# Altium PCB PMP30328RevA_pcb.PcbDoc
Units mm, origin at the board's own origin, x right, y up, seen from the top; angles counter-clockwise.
Board outline 43.18 x 40.64 mm, 2 copper layers (Top Layer, Bottom Layer), stack 1.575 mm thick; 38 components, 16 nets, 78 pads, 12 vias.
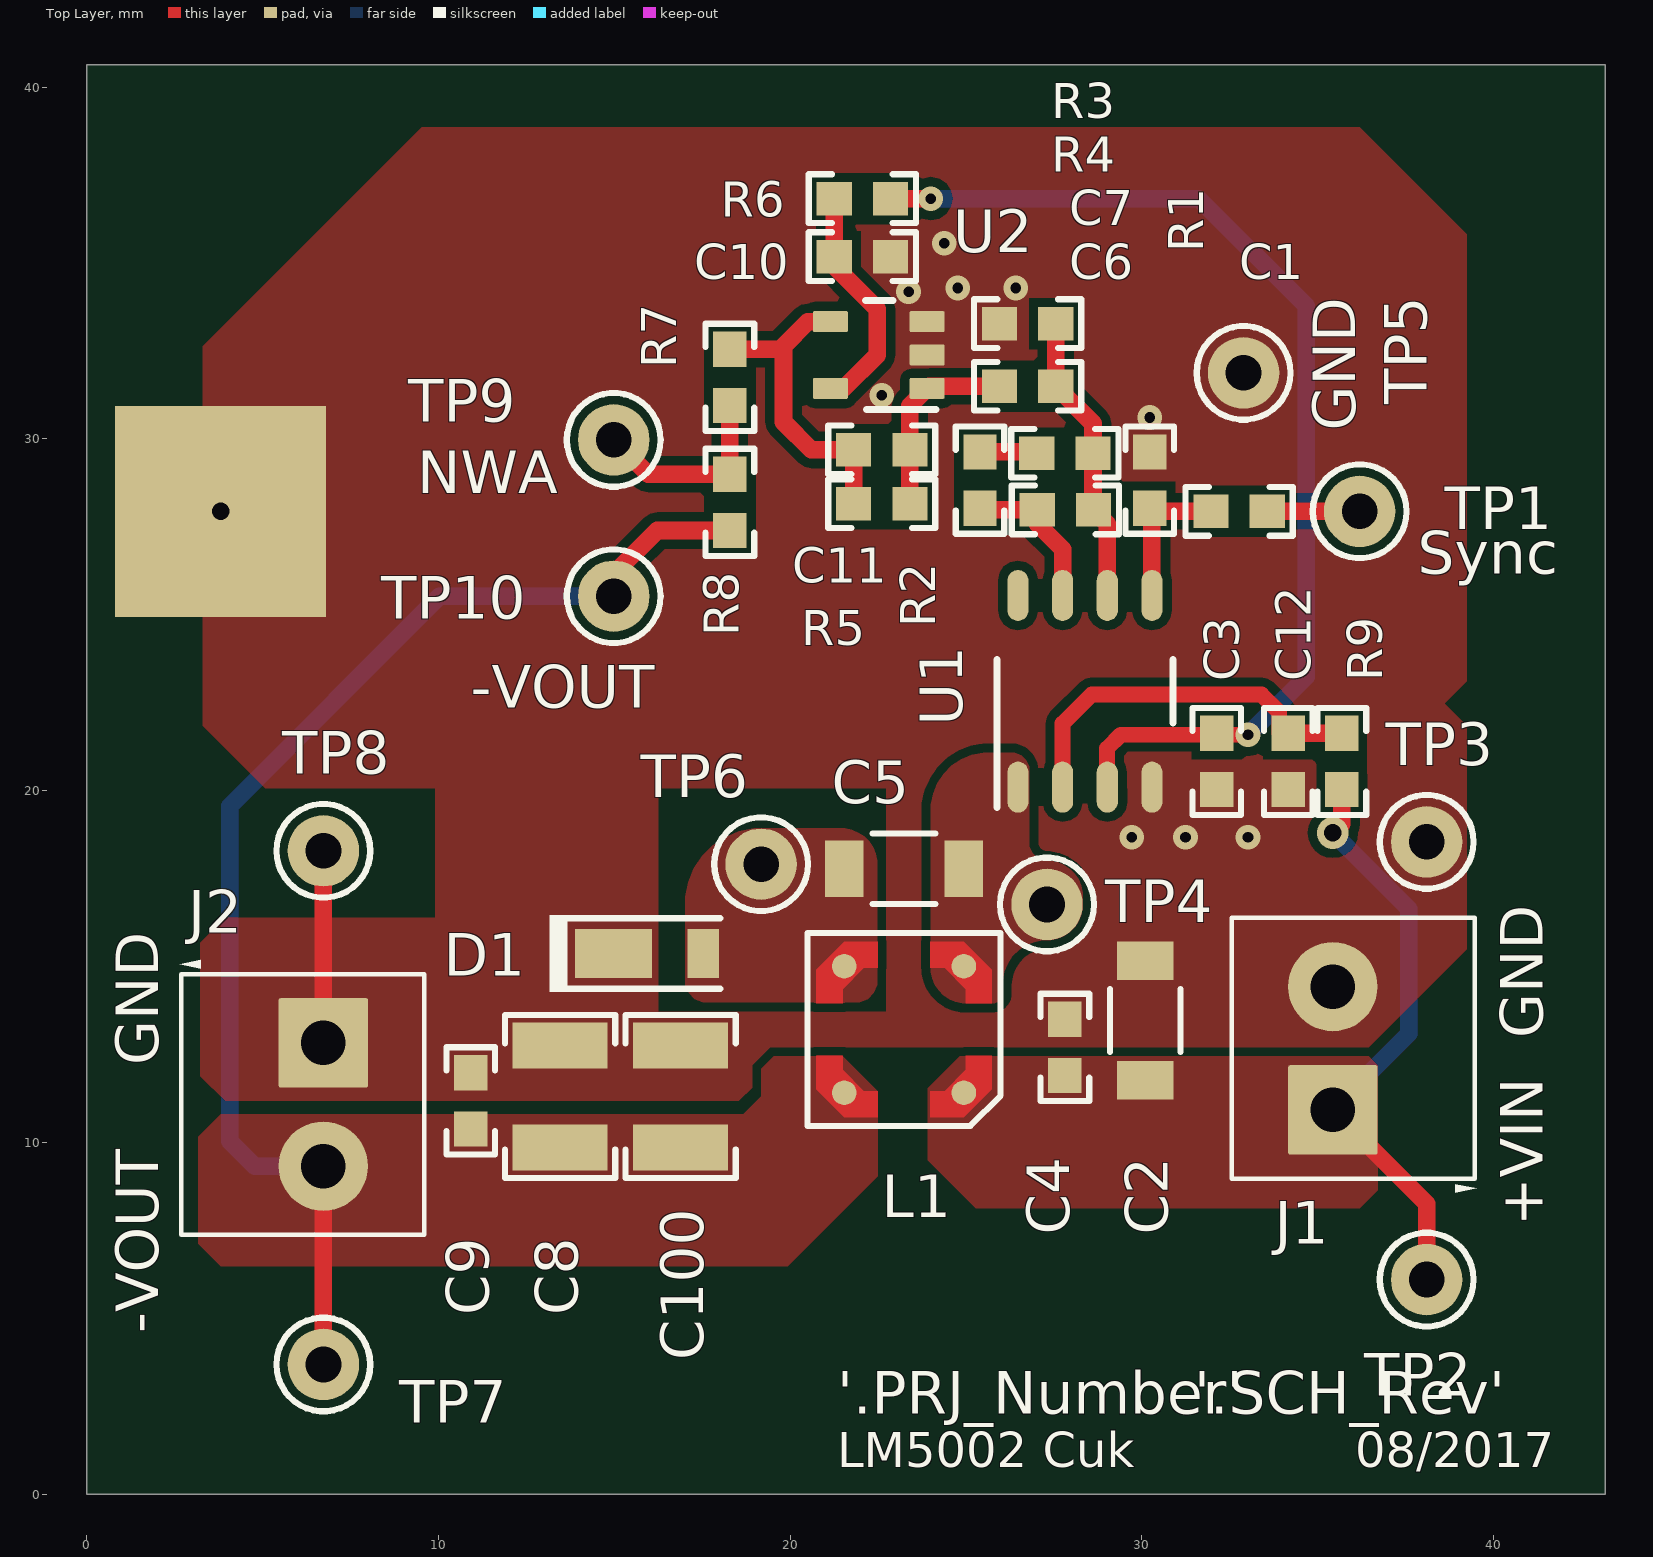
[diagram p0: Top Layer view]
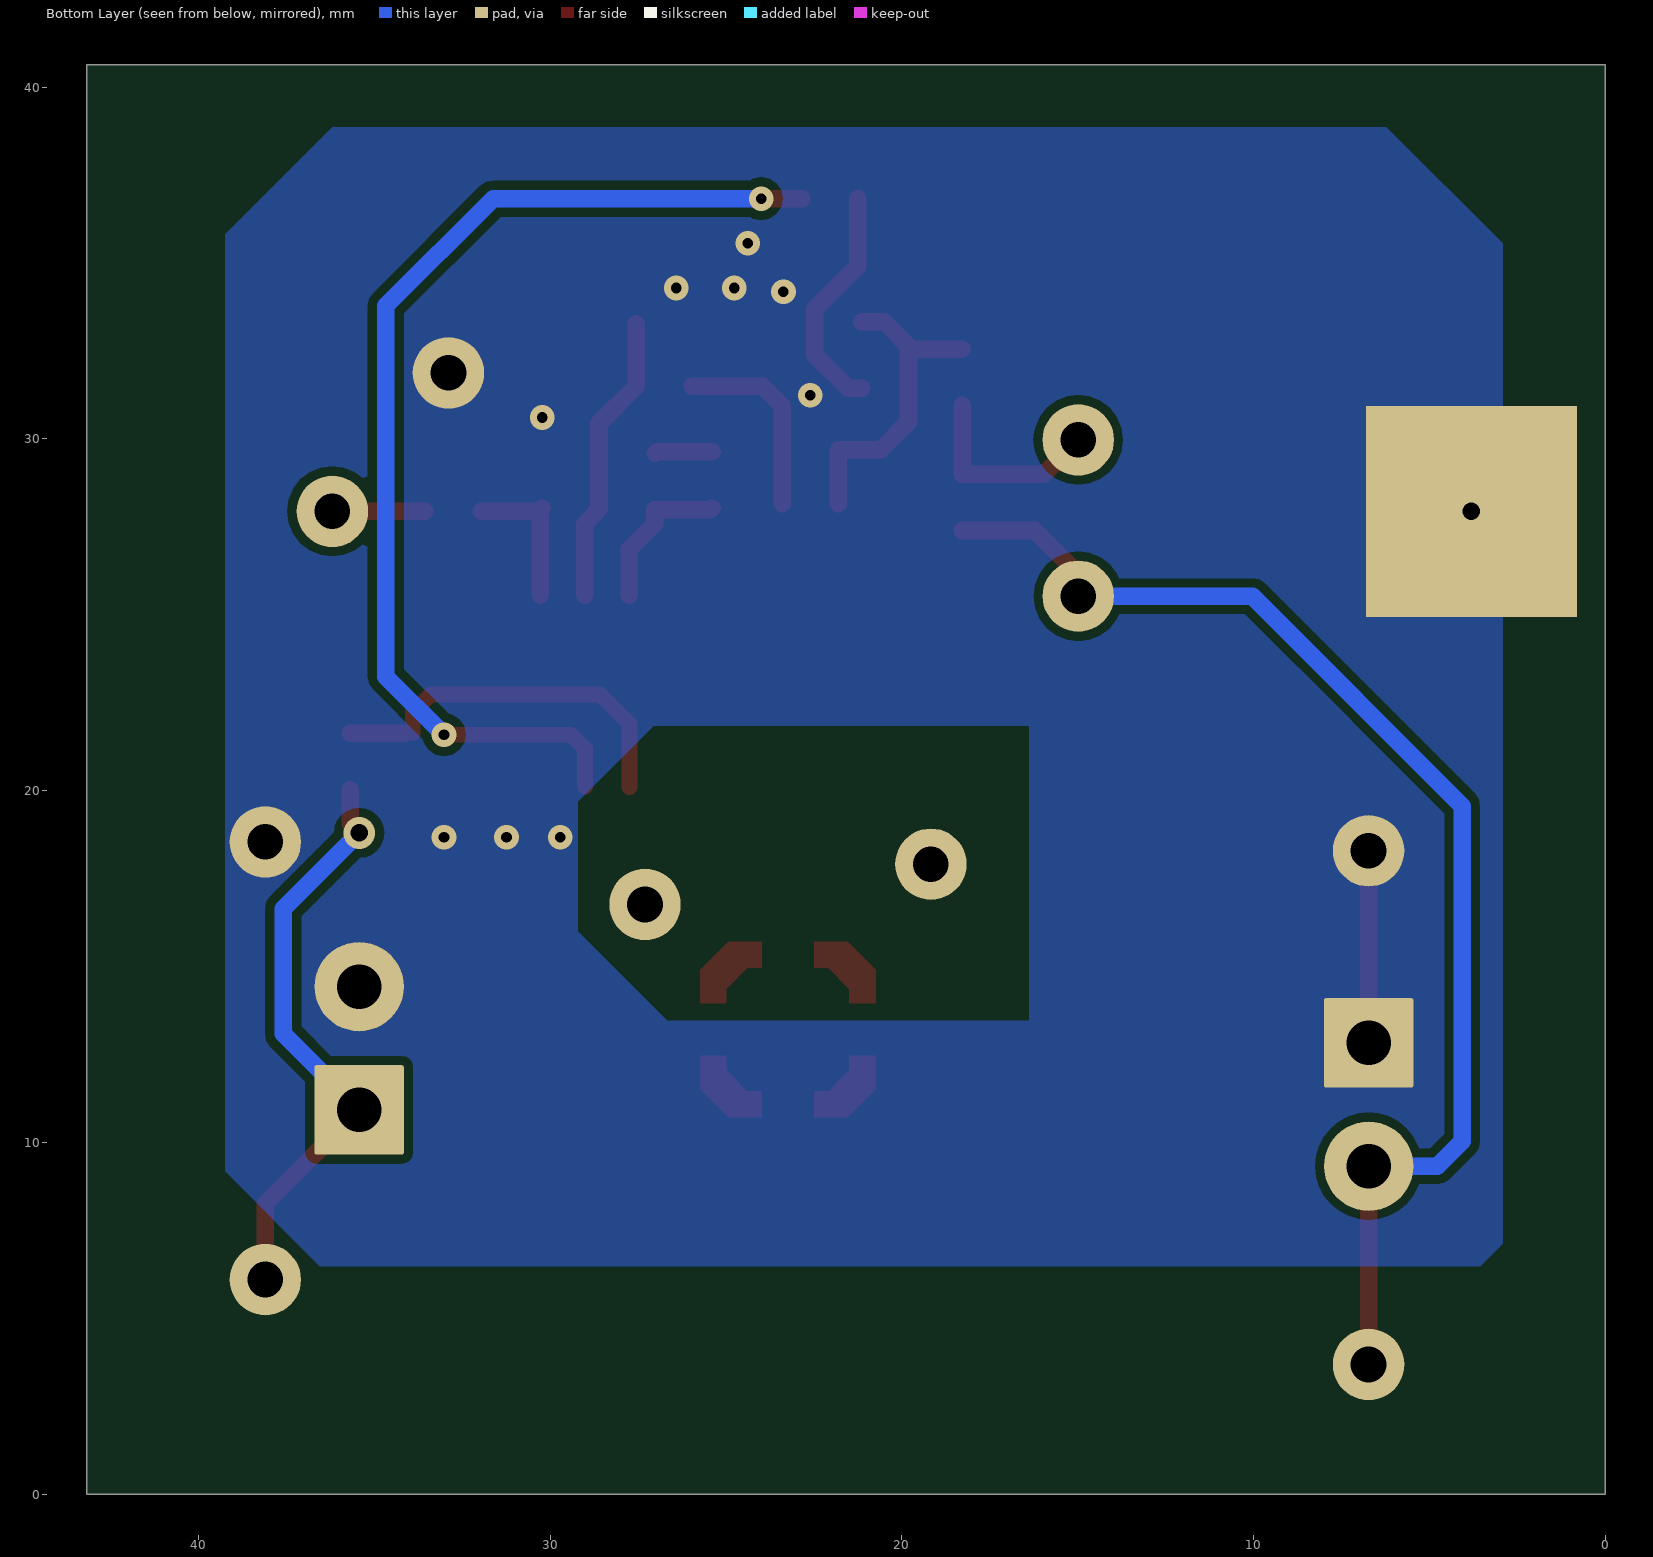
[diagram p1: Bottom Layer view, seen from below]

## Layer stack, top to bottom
Top Solder: solder mask 0.0102, Solder Resist, Dk 3.5
Top Layer: signal copper 0.0356
Dielectric1: core 1.5037, FR-4, Dk 4.8
Bottom Layer: signal copper 0.0356
Bottom Solder: solder mask 0.0102, Solder Resist, Dk 3.5

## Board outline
0,0 43.18,0 43.18,40.64 0,40.64

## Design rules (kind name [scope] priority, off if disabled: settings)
AcuteAngle [All] p1: minimum=4.50000000000000E+0001 checktracksonly=FALSE
AssemblyTestPointUsage [All] p1: valid=2
BoardOutlineClearance BoardOutlineClearance_MountingHoles [OnCopper and InComponentClass('Mounting Holes')] p1: gap=1.016 ignorepadtopadclearanceinfootprint=FALSE
BoardOutlineClearance BoardOutlineClearance_Poly [OnCopper and IsPoly] p2: gap=0.635 ignorepadtopadclearanceinfootprint=FALSE
BoardOutlineClearance [OnCopper and Not InComponentClass('Logo') and not InComponentClass('FiducialMark') and not InRegion(1000,500,4000,800) and not InPoly] p3: gap=1.905 ignorepadtopadclearanceinfootprint=FALSE
Clearance Clearance_Keepouts [((IsTrack Or IsArc) And Not InPoly) And IsFree and IsKeepOut vs ((IsTrack Or IsArc) And Not InPoly) And IsFree and IsKeepOut] p1: gap=0 ignorepadtopadclearanceinfootprint=FALSE
Clearance Clearance_Poly [InPolygon] p2: gap=0.254 ignorepadtopadclearanceinfootprint=FALSE except(0: Arc-Hole Track-Hole SMDPad-Hole THPad-Hole Via-Hole Fill-Hole Poly-Hole Region-Hole Text-Hole)
Clearance Clearance_FiducialMark [IsKeepOut and InComponentClass('FiducialMark') vs IsPad and InComponentClass('FiducialMark')] p3: gap=0 ignorepadtopadclearanceinfootprint=FALSE
Clearance [All] p4: gap=0.2 ignorepadtopadclearanceinfootprint=FALSE except(0: Text-Hole; 0.3: Arc-Hole Track-Hole SMDPad-Hole THPad-Hole Via-Hole Fill-Hole Poly-Hole Region-Hole)
ComponentClearance ComponentClearance_MountingHoles_FiducialMarks [InComponentClass('Mounting Holes') vs InComponentClass('FiducialMark')] p1: gap=1.27 collisioncheckmode=3 verticalgap=0.254 showdistances=FALSE
ComponentClearance ComponentClearance_Shunt [InComponentClass('Header') vs InComponentClass('Shunt')] p2: gap=0 collisioncheckmode=3 verticalgap=0 showdistances=FALSE
ComponentClearance ComponentClearance_Logo [InComponentClass('Logo')] p3: gap=1.27 collisioncheckmode=3 verticalgap=0.254 showdistances=FALSE
ComponentClearance ComponentClearance_ScrewToNut [(HasFootprint('NY PMS 440 0025 PH')) vs (HasFootprint('Keystone_1902C'))] p4: gap=0.127 collisioncheckmode=3 verticalgap=0.254 showdistances=FALSE
ComponentClearance ComponentClearance_MountingHoles [InComponentClass('Mounting Holes')] p5: gap=6.35 collisioncheckmode=3 verticalgap=2540 showdistances=FALSE
ComponentClearance ComponentClearance_SmallPassives [HasFootprint('0201*') or HasFootprint('0402*') or HasFootprint('0508') or HasFootprint('0603*') or HasFootprint('0612') or HasFootprint('0805*') or HasFootprint('0815*') or HasFootprint('0830*') or HasFootprint('1206*') or HasFootprint('1210*') or HasFootprint('1808*') or HasFootprint('1812*') or HasFootprint('1825*') or HasFootprint('2010*') or HasFootprint('2220*') or HasFootprint('2225*') or HasFootprint('2512*') or HasFootprint('2728*') or HasFootprint('3518*') vs HasFootprint('0201*') or HasFootprint('0402*') or HasFootprint('0508') or HasFootprint('0603*') or HasFootprint('0612') or HasFootprint('0805*') or HasFootprint('0815*') or HasFootprint('0830*') or HasFootprint('1206*') or HasFootprint('1210*') or HasFootprint('1808*') or HasFootprint('1812*') or HasFootprint('1825*') or HasFootprint('2010*') or HasFootprint('2220*') or HasFootprint('2225*') or HasFootprint('2512*') or HasFootprint('2728*') or HasFootprint('3518*')] p6: gap=0.38 collisioncheckmode=3 verticalgap=0.254 showdistances=FALSE
ComponentClearance ComponentClearance_THtoSMT [IsThruComponent vs IsSMTComponent] p7: gap=1.016 collisioncheckmode=3 verticalgap=0.762 showdistances=FALSE
ComponentClearance ComponentClearance_THtoTH [IsThruComponent vs IsThruComponent] p8: gap=0.762 collisioncheckmode=3 verticalgap=0.762 showdistances=FALSE
ComponentClearance [All] p9: gap=0.762 collisioncheckmode=3 verticalgap=0.254 showdistances=FALSE
DiffPairsRouting [All] p1: maxlimit=2.54 minlimit=0.254 mostfreqgap=0.254 toplayer_minwidth=0.381 toplayer_maxwidth=0.381 toplayer_prefwidth=0.381 bottomlayer_minwidth=0.381 bottomlayer_maxwidth=0.381 bottomlayer_prefwidth=0.381 maxuncoupledlength=25.4
FabricationTestPointUsage TestPointUsage [All] p1: valid=2 allowmultiple=FALSE
FabricationTestpoint Testpoint [All] p1: side=3 testpointundercomponent=TRUE minsize=1.016 maxsize=2.54 preferedsize=1.524 minholesize=0 maxholesize=1.016 preferedholesize=0.813 testpointgrid=0.025 allowsidetop=TRUE allowsidebottom=TRUE usegrid=TRUE gridtolerance=0
FanoutControl Fanout_LCC [IsLCC] p1: bgadir=Out bgaviamode=Centered fanoutstyle=Auto fanoutdirection=Alternating viagrid=0.025 // Fanout_LCC (Default Rule)
FanoutControl Fanout_BGA [IsBGA] p2: bgadir=Out bgaviamode=Centered fanoutstyle=Auto fanoutdirection=Alternating viagrid=0.025 // Fanout_BGA (Default Rule)
FanoutControl Fanout_Default [All] p4: bgadir=Out bgaviamode=Centered fanoutstyle=Auto fanoutdirection=Alternating viagrid=0.025 // Fanout_Default (Default Rule)
FanoutControl Fanout_Small [(CompPinCount < 5)] p5: bgadir=Out bgaviamode=Centered fanoutstyle=Auto fanoutdirection=OutThenIn viagrid=0.025 // Fanout_Small (Default Rule)
HoleSize [All] p1: absolutevalues=TRUE maxlimit=6.375 minlimit=0.3 maxpercent=80.000 minpercent=20.000
MinimumAnnularRing MinimumAnnularRing_ThermalPadVias [IsVia and InAnyComponent] p1: minimumring=0.15
MinimumAnnularRing [All] p2: minimumring=0.2
MinimumSolderMaskSliver MinimumSolderMaskSliver_Logo [InComponentClass('Logo') vs InComponentClass('Logo')] p1: minsoldermaskwidth=0.018
MinimumSolderMaskSliver [All] p2: minsoldermaskwidth=0.1
PlaneConnect [All] p1: planeconnectstyle=Relief reliefexpansion=0.254 reliefentries=4 reliefconductorwidth=0.254 reliefairgap=0.254
PolygonConnect [All] p1: connectstyle=Direct reliefconductorwidth=0.254 reliefentries=4 polygonreliefangle="90 Angle" airgapwidth=0.254
RoutingVias ThermalPadVias [IsVia and InAnyComponent] p1: holewidth=0.3 width=0.7 viastyle="Through Hole" minholewidth=0.3 minwidth=0.6 maxholewidth=0.6 maxwidth=1.6
RoutingVias [All] p2: holewidth=0.3 width=0.7 viastyle="Through Hole" minholewidth=0.3 minwidth=0.6 maxholewidth=1.016 maxwidth=2
SilkToBoardRegionClearance [Not ((IsComment or IsDesignator) And (Hide <> 'False')) and not InRegion(1000,500,4000,800)] p1:
SilkToSilkClearance SilkToSilkClearance_Pb-FreeLogo [(HasFootprint('Pb-Free_Overlay_Medium') OR HasFootprint('Pb-Free_Overlay_Small')) vs (HasFootprint('Pb-Free_Overlay_Medium') OR HasFootprint('Pb-Free_Overlay_Small'))] p1: silktosilkclearance=0
SilkToSilkClearance [All] p2: silktosilkclearance=0.102
SilkToSolderMaskClearance SilkToComponentPadClearance [(IsPad or IsFill or IsRegion) and InAnycomponent] p1: minsilkscreentomaskgap=0.127 clearancetoexposedcopper=TRUE
SilkToSolderMaskClearance "Silk to Solder Mask Opening" [All] p2: minsilkscreentomaskgap=0.102 clearancetoexposedcopper=FALSE
SolderMaskExpansion [All] p1: expansion=0.05
Width [All] p1: maxlimit=2.54 minlimit=0.152 preferedwidth=0.254 checkconnectedcopper=TRUE
15 further rules are at their usual default settings.

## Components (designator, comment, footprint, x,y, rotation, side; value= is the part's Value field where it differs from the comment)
C1 "GRM1885C1H101JA01D" 0603 32.766,27.94 r0 top value=100pF
C2 "GRM31CR72A225KA73L" 1206_190 30.099,13.462 r90 top value=2.2uF
C3 "GRM188R71E105KA12D" 0603 32.131,20.828 r270 top value=1uF
C4 "GRM188R72A104KA35D" 0603 27.813,12.7 r90 top value=0.1uF
C5 "GRM31CR72A105KA01L" 1206_180 23.241,17.78 r0 top value=1uF
C6 "GRM188R71H681KA01D" 0603 27.827,27.982 r180 top value=680pF
C7 "GRM188R71C334KA01D" 0603 27.813,29.591 r180 top value=0.33uF
C8 "GRM32ER71E226KE15L" 1210_270 13.462,11.303 r90 top value=22uF
C9 "GRM188R71E104KA01D" 0603 10.922,11.176 r90 top value=0.1uF
C10 "GRM188R71E105KA12D" 0603 22.055,35.179 r0 top value=1uF
C11 "GRM188R71H331KA01D" 0603 22.606,29.685 r0 top value=330pF
C12 "GRM188R72A104KA35D" 0603 34.163,20.828 r270 top value=0.1uF
C100 "GRM32ER71E226KE15L" 1210_270 16.891,11.303 r90 top value=22uF
D1 "DFLS1100-7" PowerDI123 16.256,15.367 r0 top value=100V
J1 "ED555/2DS" TERM_BLK_ED555-2DS 35.433,10.922 r90 top
J2 "ED555/2DS" TERM_BLK_ED555-2DS 6.731,12.827 r270 top
L1 "LPD5030V-154ME" LPD5030V 23.241,13.208 r180 top value=150uH
R1 "CRCW060342K2FKEA" 0603 30.226,28.829 r90 top value=42.2k
R2 "CRCW06034K64FKEA" 0603 25.4,28.829 r90 top value=4.64k
R3 "CRCW06033K32FKEA" 0603 26.754,33.274 r0 top value=3.32k
R4 "CRCW06034K64FKEA" 0603 26.754,31.496 r180 top value=4.64k
R5 "CRCW060310K0FKEA" 0603 22.606,28.161 r180 top value=10.0k
R6 "CRCW060310R0FKEA" 0603 22.055,36.83 r0 top value=10.0
R7 "CRCW060340K2FKEA" 0603 18.288,31.75 r270 top value=40.2k
R8 "CRCW060349R9FKEA" 0603 18.288,28.194 r270 top value=49.9
R9 "CRCW060310R0FKEA" 0603 35.687,20.828 r270 top value=10.0
TP1 "5002" Keystone5002 36.195,27.94 r270 top value=White
TP2 "5000" Keystone5000 38.1,6.096 r270 top value=Red
TP3 "5001" Keystone5001 38.1,18.542 r270 top value=Black
TP4 "5002" Keystone5002 27.305,16.764 r90 top value=White
TP5 "5001" Keystone5001 32.893,31.877 r90 top value=Black
TP6 "5002" Keystone5002 19.177,17.907 r90 top value=White
TP7 "5117" Keystone5117 6.731,3.683 r90 top value=Blue
TP8 "5001" Keystone5001 6.731,18.288 r90 top value=Black
TP9 "5004" Keystone5004 14.986,29.972 r90 top
TP10 "5000" Keystone5000 14.986,25.527 r90 top value=Red
U1 "LM5002MAX/NOPB" D0008A_N 28.384,22.823 r90 top
U2 "TLV271IDBVTG4" DBV0005A_N 22.521,32.385 r180 top

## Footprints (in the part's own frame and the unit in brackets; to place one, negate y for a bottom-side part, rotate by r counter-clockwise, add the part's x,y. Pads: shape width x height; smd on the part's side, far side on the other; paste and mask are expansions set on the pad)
0603 [mm] "0603 from SM-752 data"
  rect 1x0.95 smd: 1(-0.8,0) 2(0.8,0)
  silkscreen extent -1.52,-0.69 1.52,0.69, body extent -0.87,-0.47 0.87,0.47, height 1
1206_180 [mm] "1206_180"
  rect 1.1x1.6 smd: 1(-1.7,0) 2(1.7,0)
  silkscreen extent -0.9,-1 0.9,1, body extent -1.75,-0.95 1.75,0.95, height 1.8
1206_190 [mm] "1206_190"
  rect 1.1x1.6 smd: 1(-1.7,0) 2(1.7,0)
  silkscreen extent -0.9,-1 0.9,1, body extent -1.75,-0.95 1.75,0.95, height 1.9
1210_270 [mm] "1210"
  rect 1.3x2.7 smd: 1(-1.45,0) 2(1.45,0)
  silkscreen extent -2.32,-1.57 2.32,1.57, body extent -1.7,-1.35 1.7,1.35, height 2.7
D0008A_N [mm] "SOIC, 8-Leads, Body 4.9x3.9mm, Pitch 1.27mm, IPC Medium Density"
  oval 1.45x0.6 smd: 1(-2.725,1.905) 2(-2.725,0.635) 3(-2.725,-0.635) 4(-2.725,-1.905) 5(2.725,-1.905) 6(2.725,-0.635) 7(2.725,0.635) 8(2.725,1.905)
  silkscreen extent -3.3,-2.5 0.9,2.5, body extent -3,-2.45 3,2.45, height 1.63
DBV0005A_N [mm] "SOT23, 5-Leads, Body 2.9x1.6mm, Pitch 0.95mm, Lead Span 2.8mm, IPC Medium Density"
  rrect17% 1x0.6 smd: 1(-1.375,0.95) 2(-1.375,0) 3(-1.375,-0.95) 4(1.375,-0.95) 5(1.375,0.95)
  silkscreen extent -1.63,-1.55 0.38,1.55, body extent -1.42,-1.46 1.42,1.46, height 1.09
Keystone5000 [mil] "For Keystone 500x miniature loop terminals"
  round 80 hole 40: 1(0,0)
  silkscreen extent -52,-52 52,52, body extent -49,-49 49,49, height 182
Keystone5001 [mil] "For Keystone 500x miniature loop terminals"
  round 80 hole 40: 1(0,0)
  silkscreen extent -52,-52 52,52, body extent -49,-49 49,49, height 182
Keystone5002 [mil] "For Keystone 500x miniature loop terminals"
  round 80 hole 40: 1(0,0)
  silkscreen extent -52,-52 52,52, body extent -49,-49 49,49, height 182
Keystone5004 [mil] "For Keystone 500x miniature loop terminals"
  round 80 hole 40: 1(0,0)
  silkscreen extent -52,-52 52,52, body extent -49,-49 49,49, height 182
Keystone5117 [mil] "For Keystone 500x miniature loop terminals"
  round 80 hole 40: 1(0,0)
  silkscreen extent -52,-52 52,52, body extent -49,-49 49,49, height 182
LPD5030V [mm] "Coilcraft recommended land pattern Document 757-3 02/16/11"
  round 0.7 smd: 1(-1.7,1.8) 2(-1.7,-1.8) 3(1.7,-1.8) 4(1.7,1.8)
  Top Layer region: -1.7,-2.5 -2.5,-1.7 -2.5,-0.75 -1.75,-0.75 -1.75,-1.15 -1.15,-1.75 -0.75,-1.75 -0.75,-2.5
  Top Layer region: -2.5,0.75 -2.5,1.7 -1.7,2.5 -0.75,2.5 -0.75,1.75 -1.15,1.75 -1.75,1.15 -1.75,0.75
  Top Layer region: 0.75,1.75 0.75,2.5 1.7,2.5 2.5,1.7 2.5,0.75 1.75,0.75 1.75,1.15 1.15,1.75
  Top Layer region: 0.75,-2.5 0.75,-1.75 1.15,-1.75 1.75,-1.15 1.75,-0.75 2.5,-0.75 2.5,-1.7 1.7,-2.5
  silkscreen extent -2.74,-2.74 2.74,2.74, body extent -2.44,-2.44 2.44,2.44, height 3.02
PowerDI123 [mm] "Diodes Inc recommended land pattern, document number DS30628 Rev. 6-2"
  rect 2.2x1.4 smd: 1(-1.275,0)
  rect 0.9x1.4 smd: 2(1.275,0)
  silkscreen extent -3.1,-1.09 1.76,1.09, body extent -2.38,-0.97 1.52,0.96, height 1
TERM_BLK_ED555-2DS [mil]
  rrect4% 100x100 hole 50: 1(0,0)
  round 100 hole 50: 2(138,0)
  silkscreen extent -93,-161 215,113, body extent -69,-150 207,106, height 323

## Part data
C1: "CAP, CERM, 100 pF, 50 V,+/- 5%, C0G/NP0, 0603", Cap_Case=0603, Manufacturer=MuRata, Supplier Part Number 1=490-1427-1-ND, TempCo=C0G/NP0, Tolerance_%=5, Value1=Unknown, Value2=50V, ValueDisplayed=100pF
C2: "CAP, CERM, 2.2 µF, 100 V,+/- 10%, X7R, 1206", Cap_Case=1206, Manufacturer=MuRata, Supplier Part Number 1=490-7209-1-ND, TempCo=X7R, Tolerance_%=10, Value1=Unknown, Value2=100V, ValueDisplayed=2.2µF
C3 C10: "CAP, CERM, 1 µF, 25 V,+/- 10%, X7R, 0603", Cap_Case=0603, Manufacturer=MuRata, Supplier Part Number 1=490-5307-1-ND, TempCo=X7R, Tolerance_%=10, Value1=Unknown, Value2=25V, ValueDisplayed=1µF
C4 C12: "CAP, CERM, 0.1 µF, 100 V,+/- 10%, X7R, 0603", Cap_Case=0603, Manufacturer=MuRata, Supplier Part Number 1=490-3285-1-ND, TempCo=X7R, Tolerance_%=10, Value1=Unknown, Value2=100V, ValueDisplayed=0.1µF
C5: library part CMP-0008970-2, "CAP, CERM, 1 uF, 100 V, +/- 10%, X7R, 1206", Cap_Case=2220, Manufacturer=MuRata, Supplier Part Number 1=490-3909-1-ND, TempCo=X7R, Tolerance_%=10%, Value1=Unknown, Value2=100V, ValueDisplayed=1uF
C6: "CAP, CERM, 680 pF, 50 V,+/- 10%, X7R, 0603", Cap_Case=0603, Manufacturer=MuRata, Supplier Part Number 1=490-1491-1-ND, TempCo=X7R, Tolerance_%=10, Value1=Unknown, Value2=50V, ValueDisplayed=680pF
C7: "CAP, CERM, 0.33 µF, 16 V,+/- 10%, X7R, 0603", Cap_Case=0603, Manufacturer=MuRata, Supplier Part Number 1=490-3294-1-ND, TempCo=X7R, Tolerance_%=10, Value1=Unknown, Value2=16V, ValueDisplayed=0.33µF
C8 C100: "CAP, CERM, 22 µF, 25 V,+/- 10%, X7R, 1210", Cap_Case=1210, Manufacturer=MuRata, Supplier Part Number 1=490-5313-1-ND, TempCo=X7R, Tolerance_%=10, Value1="0.002334 ohm", Value2=25V, ValueDisplayed=22µF
C9: "CAP, CERM, 0.1 µF, 25 V,+/- 10%, X7R, 0603", Cap_Case=0603, Manufacturer=MuRata, Supplier Part Number 1=490-1524-1-ND, TempCo=X7R, Tolerance_%=10, Value2=25V, ValueDisplayed=0.1µF
C11: "CAP, CERM, 330 pF, 50 V,+/- 10%, X7R, 0603", Cap_Case=0603, Manufacturer=MuRata, Supplier Part Number 1=490-1486-1-ND, TempCo=X7R, Tolerance_%=10, Value1=Unknown, Value2=50V, ValueDisplayed=330pF
D1: "Diode, Schottky, 100 V, 1 A, PowerDI123", Manufacturer="Diodes Inc.", Supplier Part Number 1=DFLS1100DICT-ND, Value1=1A, Value2=0.77V
J1 J2: "Terminal Block, 6A, 3.5mm Pitch, 2-Pos, TH", Manufacturer="On-Shore Technology", Supplier Part Number 1=ED1514-ND
L1: "Coupled inductor, 150 µH, 0.29 A, 3.82 ohm, SMD", Manufacturer=Coilcraft, ValueDisplayed=150µH
R1: "RES, 42.2 k, 1%, 0.1 W, 0603", Manufacturer=Vishay-Dale, Power_W=0.1, Supplier Part Number 1=541-42.2KHCT-ND, TempCo="100 ppm/C", Tolerance_%=1, Value1=1%, Value2=0.1W, Value_Code=42k2, ValueDisplayed=42.2k
R2 R4: "RES, 4.64 k, 1%, 0.1 W, 0603", Manufacturer=Vishay-Dale, Power_W=0.1, Supplier Part Number 1=541-4.64KHCT-ND, TempCo="100 ppm/C", Tolerance_%=1, Value1=1%, Value2=0.1W, Value_Code=4k64, ValueDisplayed=4.64k
R3: "RES, 3.32 k, 1%, 0.1 W, 0603", Manufacturer=Vishay-Dale, Power_W=0.1, Supplier Part Number 1=541-3.32KHCT-ND, TempCo="100 ppm/C", Tolerance_%=1, Value1=1%, Value2=0.1W, Value_Code=3k32, ValueDisplayed=3.32k
R5: "RES, 10.0 k, 1%, 0.1 W, 0603", Manufacturer=Vishay-Dale, Power_W=0.1, Supplier Part Number 1=541-10.0KHCT-ND, TempCo="100 ppm/C", Tolerance_%=1, Value1=1%, Value2=0.1W, Value_Code=10k0, ValueDisplayed=10.0k
R6: "RES, 10.0, 1%, 0.1 W, 0603", Manufacturer=Vishay-Dale, Power_W=0.1, Supplier Part Number 1=541-10.0HCT-ND, TempCo="100 ppm/C", Tolerance_%=1, Value1=1%, Value2=0.1W, Value_Code=10R0, ValueDisplayed=10.0
R7: "RES, 40.2 k, 1%, 0.1 W, 0603", Manufacturer=Vishay-Dale, Power_W=0.1, Supplier Part Number 1=541-40.2KHCT-ND, TempCo="100 ppm/C", Tolerance_%=1, Value1=1%, Value2=0.1W, Value_Code=40k2, ValueDisplayed=40.2k
R8: "RES, 49.9, 1%, 0.1 W, 0603", Manufacturer=Vishay-Dale, Power_W=0.1, Supplier Part Number 1=541-49.9HCT-ND, TempCo="100 ppm/C", Tolerance_%=1, Value1=1%, Value2=0.1W, Value_Code=49R9, ValueDisplayed=49.9
R9: library part CMP-0022003-2, "RES, 10.0, 1%, 0.1 W, 0603", Manufacturer=Vishay-Dale, Power_W=100mW, Supplier Part Number 1=541-10.0HCT-ND, TempCo="100 ppm/C", Tolerance_%=1%, Value2=0.1W, Value_Code=10R0, ValueDisplayed=10.0
TP1 TP4 TP6: "Test Point, Miniature, White, TH", Manufacturer=Keystone, Supplier Part Number 1=5002K-ND
TP2 TP10: "Test Point, Miniature, Red, TH", Manufacturer=Keystone, Supplier Part Number 1=5000K-ND
TP3 TP5 TP8: "Test Point, Miniature, Black, TH", Manufacturer=Keystone, Supplier Part Number 1=5001K-ND
TP7: "Test Point, Miniature, Blue, TH", Color=Blue, Manufacturer=Keystone, Supplier Part Number 1=36-5117-ND
TP9: "Test Point, Miniature, Yellow, TH", Color=Yellow, Manufacturer=Keystone, Supplier Part Number 1=36-5004-ND
U1: library part CMP-0066117-1, "3.1-75V Wide Vin, 0.5A Current Mode Non-Synchronous Switch Mode Regulator, D0008A (SOIC-8)", Alternate Manufacturer="Texas Instruments"
U2: "550 uA/Ch, 3 MHz, Rail-to-Rail Output Operational Amplifier, 2.7 to 16 V, -40 to 125 degC, 5-pin SOT23 (DBV0005A), Green (RoHS & no Sb/Br)", Alternate Manufacturer="Texas Instruments", Alternate PartNumber=Equivalent, Rating=Catalog, Total Supply Voltage(Max)(+5V is 5, +/-5V is 10)=16, Total Supply Voltage(Min)(+5V is 5, +/-5V is 10)=2.7

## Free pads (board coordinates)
  rect 6x6 hole 0.5: 1(3.81,27.94)

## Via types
v1: diameter 0.7, hole 0.3, Top Layer to Bottom Layer, 8 vias
v2: diameter 0.7, hole 0.3, Top Layer to Bottom Layer, tented top, 3 vias
v3: diameter 0.9, hole 0.5, Top Layer to Bottom Layer, 1 vias

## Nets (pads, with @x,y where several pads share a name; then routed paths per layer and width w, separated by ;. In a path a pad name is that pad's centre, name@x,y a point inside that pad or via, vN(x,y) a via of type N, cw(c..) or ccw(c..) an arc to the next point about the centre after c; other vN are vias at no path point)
+6V9: C3.1 R6.2 U1.3 | length 31.2
  Top Layer w0.45: U1.3@29.009,20.108 29.009,21.198 29.401,21.59 v1(33.02,21.59)
  Top Layer w0.5: R6.2 v1(24.003,36.83)
  Bottom Layer w0.5: v1(24.003,36.83) 31.623,36.83 34.671,33.782 34.671,23.241 v1(33.02,21.59)
-12V0: C8.1 C9.1 C100.1 J2.2 L1.4 R8.2 TP7.1 TP10.1 | length 36
  Top Layer w0.5: TP7.1 J2.2 ; TP10.1 14.986,26.162 16.218,27.394 R8.2
  Bottom Layer w0.5: J2.2 4.775,9.322 4.064,10.033 4.064,19.558 10.033,25.527 TP10.1
GND: C2.2 C3.2 C4.2 C8.2 C9.2 C10.2 C12.2 C100.2 D1.1 J1.2 J2.1 pad.1 R1.2 R3.1 TP3.1 TP5.1 TP8.1 U1.4 U2.2 U2.3 | length 5.5
  Top Layer w0.5: J2.1 TP8.1
  other v1: 29.718,18.669 31.242,18.669 33.02,18.669 30.226,30.607 24.765,34.29 24.384,35.56
  other v2: 22.606,31.242 23.368,34.185 26.416,34.29
NetC1_1: C1.1 R1.1 U1.5 | length 4.2
  Top Layer w0.5: R1.1 R1.1@30.289,27.966 ; U1.5 R1.1@30.289,27.966 ; C1.1 30.315,27.94 R1.1@30.289,27.966
NetC1_2: C1.2 TP1.1 | length 2.6
  Top Layer w0.5: C1.2 TP1.1
NetC2_1: C2.1 C4.1 J1.1 L1.1 R9.2 TP2.1 | length 16.9
  Top Layer w0.5: J1.1 38.1,8.255 TP2.1 ; v3(35.433,18.796) 35.687,19.05 R9.2
  Bottom Layer w0.5: J1.1 37.592,13.081 37.592,16.637 v3(35.433,18.796)
NetC5_1: C5.1 D1.2 L1.3 TP6.1
NetC5_2: C5.2 L1.2 TP4.1 U1.1
NetC6_1: C6.1 C7.1 R3.2 R4.1 U1.6 | length 8.3
  Top Layer w0.5: R3.2 R4.1 28.613,30.437 C7.1 28.613,27.996 C6.1 29.019,27.59 U1.6
NetC6_2: C6.2 R2.1 U1.7 | length 4.4
  Top Layer w0.5: R2.1 25.447,27.982 C6.2 27.027,27.583 27.749,26.861 U1.7
NetC7_2: C7.2 R2.2 | length 1.6
  Top Layer w0.5: R2.2 26.975,29.629 C7.2
NetC10_1: C10.1 R6.1 U2.5 | length 6.7
  Top Layer w0.5: U2.5 21.529,31.435 22.479,32.385 22.479,33.692 21.255,34.916 C10.1 R6.1
NetC11_1: C11.1 R5.2 R7.1 U2.4 | length 9.2
  Top Layer w0.5: R7.1 19.723,32.55 19.812,32.639 ; U2.4 20.508,33.335 19.812,32.639 ; R5.2 C11.1 20.607,29.685 19.812,30.48 19.812,32.639
NetC11_2: C11.2 R4.2 R5.1 U2.1 | length 5.6
  Top Layer w0.5: R5.1 23.406,30.945 U2.1 23.957,31.496 R4.2
NetC12_1: C12.1 R9.1 U1.2 | length 10.6
  Top Layer w0.45: U1.2 27.749,21.907 28.575,22.733 33.401,22.733 33.909,22.225 C12.1@33.909,21.628
  Top Layer w0.5: C12.1 R9.1
NetR7_2: R7.2 R8.1 TP9.1 | length 5.7
  Top Layer w0.5: TP9.1 15.964,28.994 R8.1 R7.2
pads on no net: U1.8

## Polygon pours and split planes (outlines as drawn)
GND on Top Layer "TOP_LAYER_GND_P023" (solid, remove dead copper, pour order 23): 5.08,20.066 3.302,21.844 3.302,32.639 9.525,38.862 36.195,38.862 39.243,35.814 39.243,23.114 36.195,20.066
-12V0 on Top Layer "TOP_LAYER_-12V0_P013" (solid, remove dead copper, pour order 13): 22.491,11.458 22.491,9.029 19.939,6.477 3.81,6.477 3.175,7.112 3.175,10.16 3.81,10.795 16.637,10.795 18.669,10.795 19.177,11.303 19.177,12.192 19.443,12.458 21.491,12.458
GND on Top Layer "TOP_LAYER_GND_P011" (solid, remove dead copper, pour order 11): 24.384,12.7 19.431,12.7 18.923,12.192 18.923,11.557 18.542,11.176 3.937,11.176 3.231,11.882 3.231,15.677 3.937,16.383 16.256,16.383 16.256,13.716 24.384,13.716
NetC2_1 on Top Layer "TOP_LAYER_NETC2_1_P000" (solid, remove dead copper, pour order 0): 36.703,12.192 36.449,12.446 24.827,12.446 23.915,11.534 23.915,9.486 25.273,8.128 36.195,8.128 36.703,8.636
NetC5_2 on Top Layer "TOP_LAYER_NETC5_2_P015" (solid, remove dead copper, pour order 15): 26.035,14.478 cw(c27.305,14.478) 27.305,15.748 ccw(c27.305,16.764) 28.321,16.764 28.321,16.991 ccw(c27.302,16.991) 27.302,18.01 cw(c27.302,18.515) 26.797,18.515 26.797,20.574 ccw(c26.289,20.574) 26.289,21.082 25.654,21.082 ccw(c25.654,19.431) 24.003,19.431 24.003,14.946 ccw(c24.991,14.946) 24.991,13.958 25.769,13.958 ccw(c25.769,14.224) 26.035,14.224
NetC5_1 on Top Layer "TOP_LAYER_NETC5_1_P017" (solid, remove dead copper, pour order 17): 21.463,18.923 cw(c21.463,17.907) 22.479,17.907 22.479,14.605 cw(c21.844,14.605) 21.844,13.97 17.653,13.97 cw(c17.653,14.605) 17.018,14.605 17.018,16.764 cw(c19.177,16.764) 19.177,18.923
GND on Top Layer "TOP_LAYER_GND_P019" (solid, remove dead copper, pour order 19): 36.449,12.7 39.243,15.494 39.243,21.844 36.957,24.13 23.622,24.13 22.733,23.241 22.733,12.7
GND on Top Layer "TOP_LAYER_GND_P029" (solid, remove dead copper, pour order 29): 9.906,22.098 9.906,15.677 16.256,15.677 16.256,22.098
GND on Bottom Layer "BOTTOM_LAYER_GND_P027" (solid, remove dead copper, pour order 27): 2.921,34.798 14.605,34.798 16.383,33.02 16.383,8.128 14.732,6.477 3.556,6.477 2.921,7.112
GND on Bottom Layer "BOTTOM_LAYER_GND_P025" (solid, remove dead copper, pour order 25): 2.921,13.462 26.67,13.462 29.21,16.002 29.21,19.685 27.051,21.844 4.318,21.844 2.921,23.241 2.921,35.56 6.223,38.862 36.195,38.862 39.243,35.814 39.243,9.172 36.548,6.477 3.556,6.477 2.921,7.112

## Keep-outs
Keep-Out Layer:
  text ".Layer_Name" at 14.656,-21.806 h1.52

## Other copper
Top Layer:
  text ".Layer_Name" at 14.656,-21.806 h1.52
Bottom Layer:
  text ".Layer_Name" at 14.656,-21.806 h1.52

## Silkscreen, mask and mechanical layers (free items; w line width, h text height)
Top Overlay:
  text "GND" at 36.068,30.226 h1.2 r90
  text "NWA" at 9.398,28.448 h1.2
  text "Sync" at 37.846,26.162 h1.2
  text "-VOUT" at 10.922,22.352 h1.2
  text "GND" at 41.402,12.954 h1.2 r90
  text "GND" at 2.032,12.192 h1.2 r90
  text "+VIN" at 41.402,7.62 h1.2 r90
  text "-VOUT" at 2.032,4.572 h1.2 r90
  text "'.PRJ_Number'" at 21.336,2.286 h1.2
  text "'.SCH_Rev'" at 31.496,2.286 h1.2
  text "LM5002 Cuk" at 21.336,0.762 h1
  text "08/2017" at 36.068,0.762 h1
  text ".Layer_Name" at 14.656,-21.806 h1.52
Bottom Overlay:
  text ".Layer_Name" at 14.656,-21.806 h1.52
Top Paste:
  text ".Layer_Name" at 14.656,-21.806 h1.52
Bottom Paste:
  text ".Layer_Name" at 14.656,-21.806 h1.52
Top Solder:
  text ".Layer_Name" at 14.656,-21.806 h1.52
  text ".Layer_Name" at 14.656,-21.806 h1.52
Bottom Solder:
  text "'.SCH_Rev'" at 8.382,37.084 h1.2
  text "'.PRJ_Number'" at 19.05,37.084 h1.2
  text ".Layer_Name" at 14.656,-21.806 h1.52
Drill Guide:
  text ".Layer_Name" at 14.656,-21.806 h1.52
M1 Board Outline:
  the board outline again, w0.254
  text ".Layer_Name" at 14.656,-21.806 h1.52
M2 Board Dimensions:
  rectangle: 0,-6.985 3.175,-3.81
  rectangle: 3.175,-10.16 12.7,-6.985
  lines w0.178: 0,-6.985 25.4,-6.985 ; 3.175,-10.16 3.175,-3.81 ; 6.35,-10.16 6.35,-3.81 ; 12.7,-10.16 12.7,-3.81 ; 19.05,-10.16 19.05,-3.81 ; 0,-10.16 25.4,-10.16 25.4,-3.81 0,-3.81 0,-10.16
  text "'.Print_Date'" at 1.016,41.91 h1.52
  text "''.Print_Time''" at 16.637,41.91 h1.52
  text ".Layer_Name" at 14.656,-21.806 h1.52
M3 3D STEP Top:
  text ".Layer_Name" at 14.656,-21.806 h1.52
M4 3D STEP Bottom:
  text ".Layer_Name" at 14.656,-21.806 h1.52
M5 Assembly Top:
  lines w0.254: -7.417,-23.626 160.223,-23.626 ; -7.417,-18.462 160.274,-18.462 ; -7.417,-13.297 -7.417,-28.791 94.31,-28.791 160.274,-28.791 160.274,-13.297 -7.404,-13.297 -7.404,-28.791 32.614,-28.791 ; 55.194,-28.791 55.194,-13.297 ; 87.376,-18.462 87.376,-13.297 ; 108.712,-18.462 108.712,-13.297 ; 124.511,-28.956 124.511,-23.804
  text "COMPONENTS MARKED 'DNP' SHOULD NOT BE POPULATED." at 29.299,-8.09 h1.52
  text "ASSEMBLY VARIANT:" at 29.286,-11.024 h1.52
  text ".VariantName" at 55.601,-11.024 h1.52
  text "PCB VIEWED FROM TOP SIDE" at -5.804,-16.654 h1.52
  text "BOARD #:" at 57.099,-16.654 h1.52
  text ".PRJ_Number" at 70.955,-16.654 h1.52
  text "REV:" at 92.405,-16.654 h1.52
  text ".PCB_Rev" at 99.809,-16.654 h1.52
  text "SVN REV:" at 113.69,-16.654 h1.52
  text ".VersionControl_RevNumber" at 126.543,-16.654 h1.52
  text "TID #:" at 57.099,-21.819 h1.52
  text ".TID" at 70.955,-21.819 h1.52
  text "PLOT NAME =" at -5.804,-27.034 h1.52
  text ".plot_File_Name" at 14.656,-27.034 h1.52
  text "GENERATED    :" at 57.15,-27.034 h1.52
  text ".Print_Date" at 79.235,-27.034 h1.52
  text ".Print_Time" at 97.752,-27.034 h1.52
  text "TEXAS INSTRUMENTS" at 129.87,-27.034 h1.52
M6 Assembly Bottom:
  lines w0.254: -7.429,-18.474 160.261,-18.474 ; -7.379,-23.639 160.261,-23.639 ; 28.334,-28.969 28.334,-23.817 ; 44.133,-18.474 44.133,-13.31 ; 65.468,-18.474 65.468,-13.31 ; 97.65,-28.804 97.65,-13.31 ; 120.231,-28.804 160.249,-28.804 160.249,-13.31 -7.429,-13.31 -7.429,-28.804 58.534,-28.804 160.261,-28.804 160.261,-13.31
  text "COMPONENTS MARKED 'DNP' SHOULD NOT BE POPULATED." at 154.991,-8.077 h1.52
  text ".VariantName" at 128.473,-11.024 h1.52
  text "ASSEMBLY VARIANT:" at 154.864,-11.024 h1.52
  text ".VersionControl_RevNumber" at 26.302,-16.667 h1.52
  text "SVN REV:" at 39.154,-16.667 h1.52
  text ".PCB_Rev" at 53.035,-16.667 h1.52
  text "REV:" at 60.439,-16.667 h1.52
  text ".PRJ_Number" at 81.89,-16.667 h1.52
  text "BOARD #:" at 95.745,-16.667 h1.52
  text "PCB VIEWED FROM BOTTOM SIDE" at 158.648,-16.667 h1.52
  text ".TID" at 81.89,-21.831 h1.52
  text "TID #:" at 95.745,-21.831 h1.52
  text "TEXAS INSTRUMENTS" at 22.974,-27.047 h1.52
  text ".Print_Time" at 55.093,-27.047 h1.52
  text ".Print_Date" at 73.609,-27.047 h1.52
  text "GENERATED    :" at 95.694,-27.047 h1.52
  text ".plot_File_Name" at 138.189,-27.047 h1.52
  text "PLOT NAME =" at 158.648,-27.047 h1.52
M9 Title Sheet:
  drawing of 57 lines, arcs and shapes, not listed
  text "1" at 18.792,204.127 h1.78
  text "2" at 82.182,204.127 h1.78
  text "3" at 145.411,204.127 h1.78
  text "4" at 209.08,204.127 h1.78
  text "5" at 272.555,204.127 h1.78
  text "6" at 336.182,204.127 h1.78
  text "A" at -10.579,175.095 h1.78
  text "A" at 365.341,175.095 h1.78
  text "B" at -10.579,114.643 h1.78
  text "B" at 365.341,114.643 h1.78
  text "C" at -10.579,54.318 h1.78
  text "C" at 365.341,54.318 h1.78
  text "PROJECT TITLE:" at 288.125,7.048 h1.14
  text ".PRJ_Title" at 289.395,3.662 h1.78
  text "DESIGNED FOR:" at 288.125,-0.597 h1.14
  text ".PRJ_Customer" at 289.395,-4.153 h1.78
  text "D" at -10.579,-5.88 h1.78
  text "D" at 365.341,-5.88 h1.78
  text "FILE NAME:" at 288.125,-8.217 h1.14
  text ".PCB_File_Name_No_Path" at 289.395,-11.265 h1.78
  text "Texas Instruments (TI) and/or its licensors do not warrant the accuracy or completeness of this specification" at 161.9,-15.376 h1.14
  text "ENGINEER:" at 288.125,-15.583 h1.14
  text "LAYOUT BY:" at 326.352,-15.583 h1.14
  text "or any information contained therein. TI and/or its licensors do not warrant that this design will meet" at 160.757,-18.237 h1.14
  text ".PRJ_Engineer" at 289.395,-19.52 h1.78
  text ".PCB_Layout" at 327.635,-19.52 h1.78
  text "the specifications, will be suitable for your application or fit for any particular purpose, or will operate in" at 160.757,-21.099 h1.14
  text ".Layer_Name" at 14.656,-21.806 h1.52
  text "ALTIUM DESIGNER VERSION:" at 326.352,-23.457 h1.14
  text "an implementation. TI and/or its licensors do not warrant that the design is production worthy. You should" at 160.757,-23.961 h1.14
  text "completely validate and test your design implementation to confirm the system functionality for your application." at 161.9,-26.822 h1.14
  text ".print_Scale" at 289.395,-26.843 h1.78
  text ".Application_BuildNumber" at 327.635,-26.843 h1.78
  text "1" at 18.792,-32.093 h1.78
  text "2" at 82.182,-32.093 h1.78
  text "3" at 145.411,-32.093 h1.78
  text "4" at 209.08,-32.093 h1.78
  text "5" at 272.555,-32.093 h1.78
  text "6" at 336.182,-32.093 h1.78
M10 Fab Notes:
  drawing of 189 lines, arcs and shapes, not listed
  text "DESIGN INFORMATION" at 314.503,161.447 h1.52
  text "MIN. TRACK WIDTH:" at 298.131,158.091 h1.52
  text "8" at 325.976,158.091 h1.52
  text "MIL" at 329.907,158.091 h1.52
  text "MIN. CLEARANCE:" at 298.131,154.938 h1.52
  text "0.2" at 324.452,154.938 h1.52
  text "mm" at 329.907,154.938 h1.52
  text "MIN. VIA PAD SIZE:" at 298.131,151.785 h1.52
  text "24" at 325.214,151.785 h1.52
  text "MIL" at 329.907,151.785 h1.52
  text "0.05mm (2MIL)" at 315.784,148.486 h1.52
  text "MINIMUM ANNULAR RING" at 289.769,148.277 h1.52
  text "EXTERNAL" at 333.768,148.277 h1.52
  text "PER" at 294.849,145.48 h1.52
  text "IPC-D-275 CLASS 2 LEVEL C" at 300.437,145.48 h1.52
  text "MIL, HOLES" at 338.238,142.928 h1.52
  text "+/-" at 328.27,142.709 h1.52
  text "+/-" at 349.961,142.709 h1.52
  text "REGISTRATION TOLERANCES:" at 289.769,142.682 h1.52
  text "METAL" at 320.243,142.682 h1.52
  text "5" at 334.879,142.683 h1.52
  text "3" at 356.037,142.683 h1.52
  text "MIL" at 358.99,142.682 h1.52
  text "HOLE SIZE TOLERANCE (UNLESS OTHERWISE SPECIFIED):" at 289.769,140.185 h1.52
  text "+/-" at 349.961,140.112 h1.52
  text "3" at 356.037,140.085 h1.52
  text "MIL" at 358.99,140.085 h1.52
  text "MATERIAL:" at 287.87,136.589 h1.52
  text "FR-4 High Tg" at 312.926,133.324 h1.52
  text "X" at 309.257,133.122 h1.52
  text "FR-408" at 298.563,133.007 h1.52
  text "OTHER" at 336.358,133.007 h1.52
  text "62 MIL (1.6mm) +/-10%" at 306.694,129.374 h1.52
  text "X" at 303.643,129.312 h1.52
  text "THICKNESS:" at 289.769,129.165 h1.52
  text "OTHER" at 339.33,129.165 h1.52
  text "TOLERANCE:" at 289.769,125.652 h1.52
  text "X" at 311.314,125.652 h1.52
  text "ANSI IPC-6012 TYPE 3 CLASS 2" at 315.836,125.652 h1.52
  text "OTHER +/-" at 315.835,121.989 h1.52
  text "BOW & TWIST:" at 289.769,118.302 h1.52
  text "X" at 311.314,118.302 h1.52
  text "ANSI IPC-6012 TYPE 3 CLASS 2" at 315.836,118.302 h1.52
  text "OTHER +/-" at 315.835,114.576 h1.52
  text "DRILLING:" at 287.87,111.258 h1.52
  text "NC_DRILL FILES" at 332.599,108.586 h1.52
  text "REFERENCE:" at 289.769,108.486 h1.52
  text "X" at 306.463,108.484 h1.52
  text "AS SHOWN" at 310.984,108.486 h1.52
  text "X" at 329.348,108.486 h1.52
  text "OTHER" at 340.168,104.873 h1.52
  text "PTH COPPER THICKNESS:" at 289.761,104.783 h1.52
  text "X" at 318.697,104.783 h1.52
  text "20-30 um" at 321.948,104.783 h1.52
  text "BOARD FINISH:" at 287.87,101.034 h1.52
  text "SILKSCREEN:" at 291.812,98.237 h1.52
  text "X" at 316.14,98.237 h1.52
  text "TOP" at 319.112,98.237 h1.52
  text "X" at 329.094,98.237 h1.52
  text "BOTTOM" at 332.091,98.237 h1.52
  text "SILKSCREEN COLOR:" at 291.812,94.295 h1.52
  text "X" at 316.115,94.295 h1.52
  text "WHITE" at 319.112,94.295 h1.52
  text "OTHER" at 332.091,94.295 h1.52
  text "X" at 319.442,90.652 h1.52
  text "GREEN" at 322.439,90.652 h1.52
  text "OTHER" at 338.136,90.652 h1.52
  text "SOLDER RESIST COLOR:" at 291.812,90.477 h1.52
  text "X" at 319.442,86.734 h1.52
  text "MATTE" at 322.439,86.734 h1.52
  text "SEMI-GLOSS" at 338.125,86.717 h1.52
  text "IMMERSION GOLD (ENIG)" at 314.819,82.345 h1.52
  text "ENEPIG" at 348.793,82.162 h1.52
  text "SURFACE FINISH:" at 287.87,82.136 h1.52
  text "X" at 310.298,82.136 h1.52
  text "IMM. TIN/SILVER OR EQUIV" at 296.24,78.649 h1.52
  text "OTHER" at 332.599,78.549 h1.52
  text "ARRAY/PANEL:" at 287.87,74.602 h1.52
  text "CUT AND TRIM PER M1 BOARD OUTLINE" at 314.819,74.393 h1.52
  text "N.C. ROUTE" at 314.819,70.94 h1.52
  text "X" at 332.295,70.94 h1.52
  text "V. SCORE" at 336.816,70.94 h1.52
  text "CERTIFICATION:" at 287.87,67.66 h1.52
  text "MATERIALS AND WORKMANSHIP FOR ALL PCBS" at 306.285,67.66 h1.52
  text "TO MEET OR EXCEED THE REQUIREMENTS OF:" at 306.285,65.271 h1.52
  text "X" at 297.078,62.003 h1.52
  text "ANSI IPC-A-600F CLASS ->" at 300.329,62.003 h1.52
  text "X" at 342.188,62.003 h1.52
  text "2" at 344.982,62.003 h1.52
  text "1" at 336.981,61.965 h1.52
  text "3" at 353.973,61.965 h1.52
  text "X" at 317.702,58.252 h1.52
  text "RoHS" at 320.953,58.252 h1.52
  text "OTHER" at 337.321,58.252 h1.52
  text "PER ORDER" at 347.407,58.252 h1.52
  text "ALL BOARDS MUST MEET OR EXCEED UL94-V0 REQUIREMENTS." at 288.569,54.345 h1.52
  text "PCB MUST BEAR THE UL94V-0 UL REGISTERED MATERIAL ID NUMBER" at 288.569,51.397 h1.52
  text "ADDITIONAL REQUIREMENTS:" at 287.87,47.094 h1.52
  text "MICROSECTION:" at 289.769,44.373 h1.52
  text "YES" at 312.775,44.373 h1.52
  text "REQUIRED" at 334.657,40.707 h1.52
  text "BARE BOARD ELEC. TEST:" at 289.769,40.634 h1.52
  text "NONE" at 322.935,40.634 h1.52
  text "X" at 331.66,40.634 h1.52
  text "PER ORDER" at 349.693,40.634 h1.52
  text "XX MIL VIAS REQUIRE NON-CONDUCTIVE FILL AND PLANARIZE" at 294.04,35.428 h1.5
  text "XX MIL VIAS REQUIRE CONDUCTIVE FILL AND PLANARIZE" at 294.243,32.787 h1.52
  text "OUTER XX MIL VIAS REQUIRE 50 OHM SINGLE-ENDED IMPEDANCE" at 294.218,28.637 h1.47
  text "LAYER 2 & 3 (INNER LAYERS) XX MIL WIDE, XX MIL SPACE / TRACES REQUIRE 100 OHM DIFFERENTIAL IMPEDANCE" at 294.015,22.65 h1.52
  text ".Layer_Name" at 152.927,8.535 h1.52
  text ".Layer_Name" at 14.656,-21.806 h1.52
M11 Gerber Information:
  lines w0.254: -7.417,-23.626 160.223,-23.626 ; -7.417,-18.462 160.274,-18.462 ; -7.417,-13.297 -7.417,-28.791 94.31,-28.791 160.274,-28.791 160.274,-13.297 -7.404,-13.297 -7.404,-28.791 32.614,-28.791 ; 55.194,-28.791 55.194,-13.297 ; 87.376,-18.462 87.376,-13.297 ; 108.712,-18.462 108.712,-13.297 ; 124.511,-28.956 124.511,-23.804
  text "ALL ARTWORK VIEWED FROM TOP SIDE" at -5.804,-16.654 h1.52
  text "BOARD #:" at 57.099,-16.654 h1.52
  text ".PRJ_Number" at 70.955,-16.654 h1.52
  text "REV:" at 92.405,-16.654 h1.52
  text ".PCB_Rev" at 99.809,-16.654 h1.52
  text "SVN REV:" at 113.69,-16.654 h1.52
  text ".VersionControl_RevNumber" at 126.543,-16.654 h1.52
  text "LAYER NAME =" at -5.804,-21.806 h1.52
  text "TID #:" at 57.099,-21.819 h1.52
  text ".TID" at 70.955,-21.819 h1.52
  text "PLOT NAME =" at -5.804,-27.034 h1.52
  text ".plot_File_Name" at 14.656,-27.034 h1.52
  text "GENERATED    :" at 57.15,-27.034 h1.52
  text ".Print_Date" at 79.235,-27.034 h1.52
  text ".Print_Time" at 97.752,-27.034 h1.52
  text "TEXAS INSTRUMENTS" at 129.87,-27.034 h1.52
M12 Stackup:
  drawing of 191 lines, arcs and shapes, not listed
  text "Layer" at 248.675,198.882 h1.52
  text "Name" at 259.086,198.882 h1.52
  text "Material" at 282.702,198.882 h1.52
  text "Thickness" at 304.54,198.882 h1.52
  text "Constant" at 321.046,198.882 h1.52
  text "Board Layer Stack" at 335.52,198.882 h1.52
  text "1" at 248.675,195.834 h1.52
  text "Top Overlay" at 259.086,195.834 h1.52
  text "2" at 248.675,192.786 h1.52
  text "Top Solder" at 259.086,192.786 h1.52
  text "Solder Resist" at 282.702,192.786 h1.52
  text "0.40mil" at 304.54,192.786 h1.52
  text "3.5" at 321.046,192.786 h1.52
  text "3" at 248.675,189.738 h1.52
  text "Top Layer" at 259.086,189.738 h1.52
  text "Copper" at 282.702,189.738 h1.52
  text "1.40mil" at 304.54,189.738 h1.52
  text "4" at 248.675,186.69 h1.52
  text "Dielectric1" at 259.086,186.69 h1.52
  text "FR-4" at 282.702,186.69 h1.52
  text "59.20mil" at 304.54,186.69 h1.52
  text "4.8" at 321.046,186.69 h1.52
  text "5" at 248.675,183.642 h1.52
  text "Bottom Layer" at 259.086,183.642 h1.52
  text "Copper" at 282.702,183.642 h1.52
  text "1.40mil" at 304.54,183.642 h1.52
  text "6" at 248.675,180.594 h1.52
  text "Bottom Solder" at 259.086,180.594 h1.52
  text "Solder Resist" at 282.702,180.594 h1.52
  text "0.40mil" at 304.54,180.594 h1.52
  text "3.5" at 321.046,180.594 h1.52
  text "7" at 248.675,177.546 h1.52
  text "Bottom Overlay" at 259.086,177.546 h1.52
  text ".Layer_Name" at 14.656,-21.806 h1.52
M13 Component Bodies Top:
  text ".Layer_Name" at 14.656,-21.806 h1.52
M14 Component Bodies Bottom:
  text ".Layer_Name" at 14.656,-21.806 h1.52
M15 Courtyards Top:
  text ".Layer_Name" at 14.656,-21.806 h1.52
M16 Courtyards Bottom:
  text ".Layer_Name" at 14.656,-21.806 h1.52
Drill Drawing:
  circle w0.254: c136.241,73.47 r0.703
  lines w0.254: 135.538,75.929 136.944,75.929 136.944,77.335 135.538,77.335 135.538,75.929 ; 135.538,80.497 136.944,80.497 136.241,79.092 135.538,80.497 ; 135.538,82.605 135.89,82.605 136.241,82.254 136.593,82.605 136.944,82.605 136.593,82.957 136.944,83.308 136.593,83.308 136.241,83.66 135.89,83.308 135.538,83.308 135.89,82.957 135.538,82.605
  lines w0.305: 134.264,71.819 216.362,71.819 ; 134.264,84.468 216.362,84.468 ; 142.85,68.656 142.85,87.63 ; 151.287,68.656 151.287,87.63 ; 167.453,68.656 167.453,87.63 ; 174.037,68.656 174.037,87.63 ; 183.568,68.656 183.568,87.63 ; 201.972,68.656 201.972,87.63 ; 134.264,68.656 216.362,68.656 216.362,87.63 134.264,87.63 134.264,68.656
  text "Symbol" at 136.162,85.416 h1.83
  text "Quantity" at 143.799,85.416 h1.83
  text "Finished Hole Size" at 152.235,85.416 h1.83
  text "Plated" at 168.402,85.416 h1.83
  text "Hole Type" at 174.986,85.416 h1.83
  text "Drill Layer Pair" at 184.517,85.416 h1.83
  text "Hole Tolerance" at 202.92,85.416 h1.83
  text "11" at 143.799,82.254 h1.52
  text "11.81mil (0.300mm)" at 152.235,82.254 h1.52
  text "PTH" at 168.402,82.254 h1.52
  text "Round" at 174.986,82.254 h1.52
  text "Top Layer - Bottom Layer" at 184.517,82.254 h1.52
  text "2" at 143.799,79.092 h1.52
  text "19.69mil (0.500mm)" at 152.235,79.092 h1.52
  text "PTH" at 168.402,79.092 h1.52
  text "Round" at 174.986,79.092 h1.52
  text "Top Layer - Bottom Layer" at 184.517,79.092 h1.52
  text "10" at 143.799,75.929 h1.52
  text "40.00mil (1.016mm)" at 152.235,75.929 h1.52
  text "PTH" at 168.402,75.929 h1.52
  text "Round" at 174.986,75.929 h1.52
  text "Top Layer - Bottom Layer" at 184.517,75.929 h1.52
  text "4" at 143.799,72.767 h1.52
  text "50.00mil (1.270mm)" at 152.235,72.767 h1.52
  text "PTH" at 168.402,72.767 h1.52
  text "Round" at 174.986,72.767 h1.52
  text "Top Layer - Bottom Layer" at 184.517,72.767 h1.52
  text "27 Total" at 143.799,69.605 h1.52
  text ".Layer_Name" at 14.656,-21.806 h1.52
M17 Embedded Cavity:
  text ".Layer_Name" at 14.656,-21.806 h1.52
M18 Embedded Assembly:
  text ".Layer_Name" at 14.656,-21.806 h1.52
M19 Embedded Keepout:
  text ".Layer_Name" at 14.656,-21.806 h1.52

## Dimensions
0,-10.16 to 25.4,-10.16 on M2 Board Dimensions
0,0 to 0,40.64 on M2 Board Dimensions
0,0 to 43.18,0 on M2 Board Dimensions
